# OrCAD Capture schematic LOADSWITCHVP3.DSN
size A
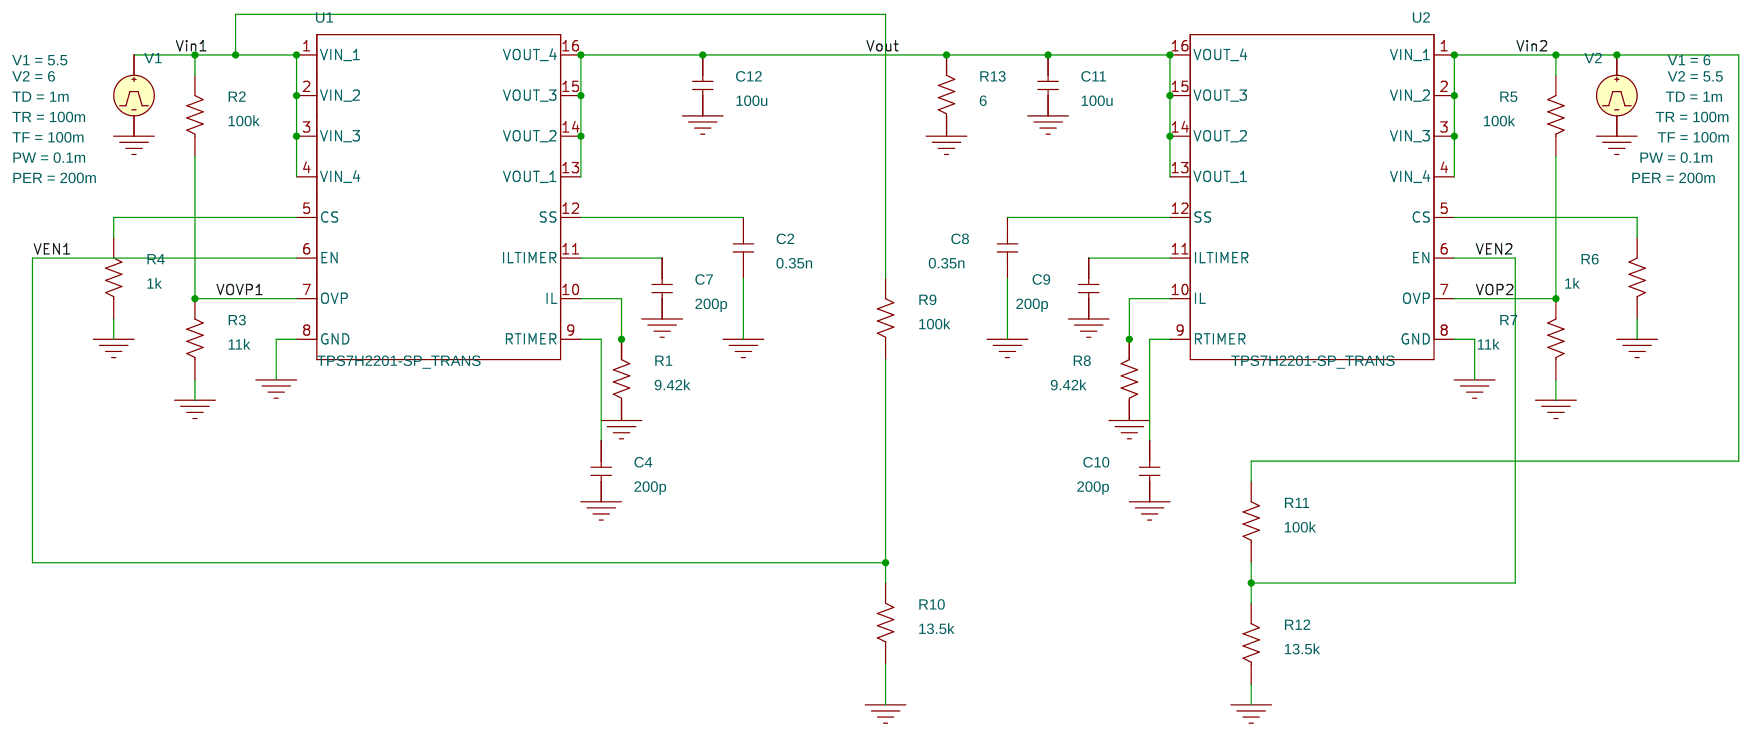
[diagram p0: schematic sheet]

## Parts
C2  0.35n  [cap196]
C4  200p  [cap196]
C7  200p  [cap196]
C8  0.35n  [cap196]
C9  200p  [cap196]
C10  200p  [cap196]
C11  100u  [cap196]
C12  100u  [cap196]
R1  9.42k  [AXRC05]
R2  100k  [AXRC05]
R3  11k  [AXRC05]
R4  1k  [AXRC05]
R5  100k  [AXRC05]
R6  1k  [AXRC05]
R7  11k  [AXRC05]
R8  9.42k  [AXRC05]
R9  100k  [AXRC05]
R10  13.5k  [AXRC05]
R11  100k  [AXRC05]
R12  13.5k  [AXRC05]
R13  6  [AXRC05]
U1  TPS7H2201-SP_TRANS  [PWP0016M_N]
U2  TPS7H2201-SP_TRANS  [PWP0016M_N]
V1  VPULSE
V2  VPULSE

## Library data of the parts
C2 C4 C7-C12 = C
R1-R13 = R
U1 U2 = TPS7H2201-SP_TRANS
V1 = VPULSE: PER: 200m; PW: 0.1m; TD: 1m; TF: 100m; TR: 100m; V1: 5.5; V2: 6
V2 = VPULSE: PER: 200m; PW: 0.1m; TD: 1m; TF: 100m; TR: 100m; V1: 6; V2: 5.5

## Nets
Vin1: R2.2 R9.2 U1.1(VIN) U1.2(VIN) U1.3(VIN) U1.4(VIN) V1.1(+)
Vin2: R5.2 R11.2 U2.1(VIN) U2.2(VIN) U2.3(VIN) U2.4(VIN) V2.1(+)
0: C2.1 C4.1 C7.1 C8.1 C9.1 C10.1 C11.1 C12.1 R1.1 R3.1 R4.1 R6.1 R7.1 R8.1 R10.1 R12.1 R13.1 U1.8(GND) U2.8(GND) V1.2(-) V2.2(-)
VEN1: R9.1 R10.2 U1.6(EN)
VEN2: R11.1 R12.2 U2.6(EN)
VOP2: R5.1 R7.2 U2.7(OVP)
Vout: C11.2 C12.2 R13.2 U1.13(VOUT_1) U1.14(VOUT_2) U1.15(VOUT_3) U1.16(VOUT_4) U2.13(VOUT_1) U2.14(VOUT_2) U2.15(VOUT_3) U2.16(VOUT_4)
VOVP1: R2.1 R3.2 U1.7(OVP)
N00631: C2.2 U1.12(SS)
N00834: C7.2 U1.11(ILTIMER)
N00859: R1.2 U1.10(IL)
N00888: C4.2 U1.9(RTIMER)
N01236: R4.2 U1.5(CS)
N02352: R6.2 U2.5(CS)
N02360: C8.2 U2.12(SS)
N02396: C9.2 U2.11(ILTIMER)
N02424: R8.2 U2.10(IL)
N02476: C10.2 U2.9(RTIMER)
